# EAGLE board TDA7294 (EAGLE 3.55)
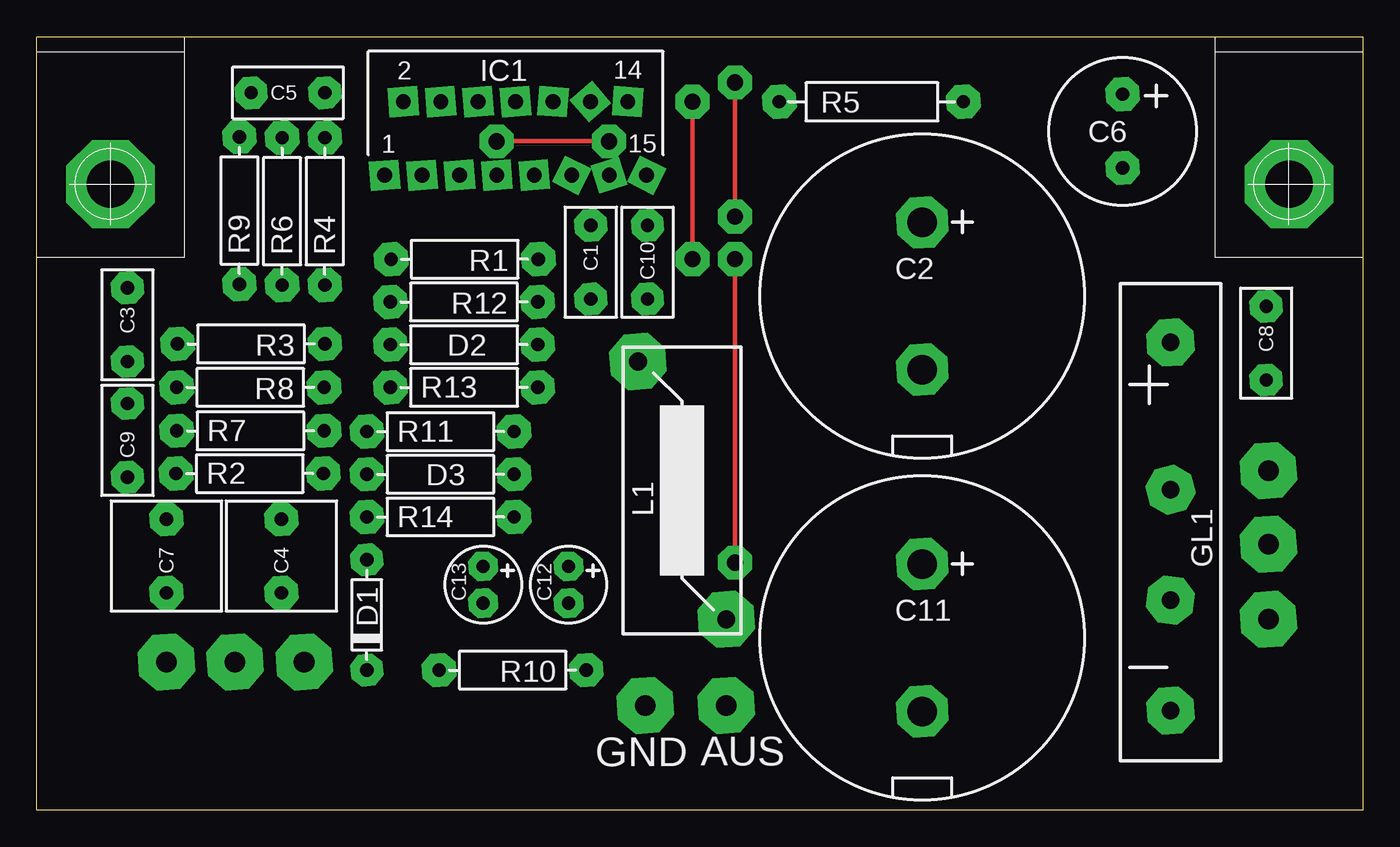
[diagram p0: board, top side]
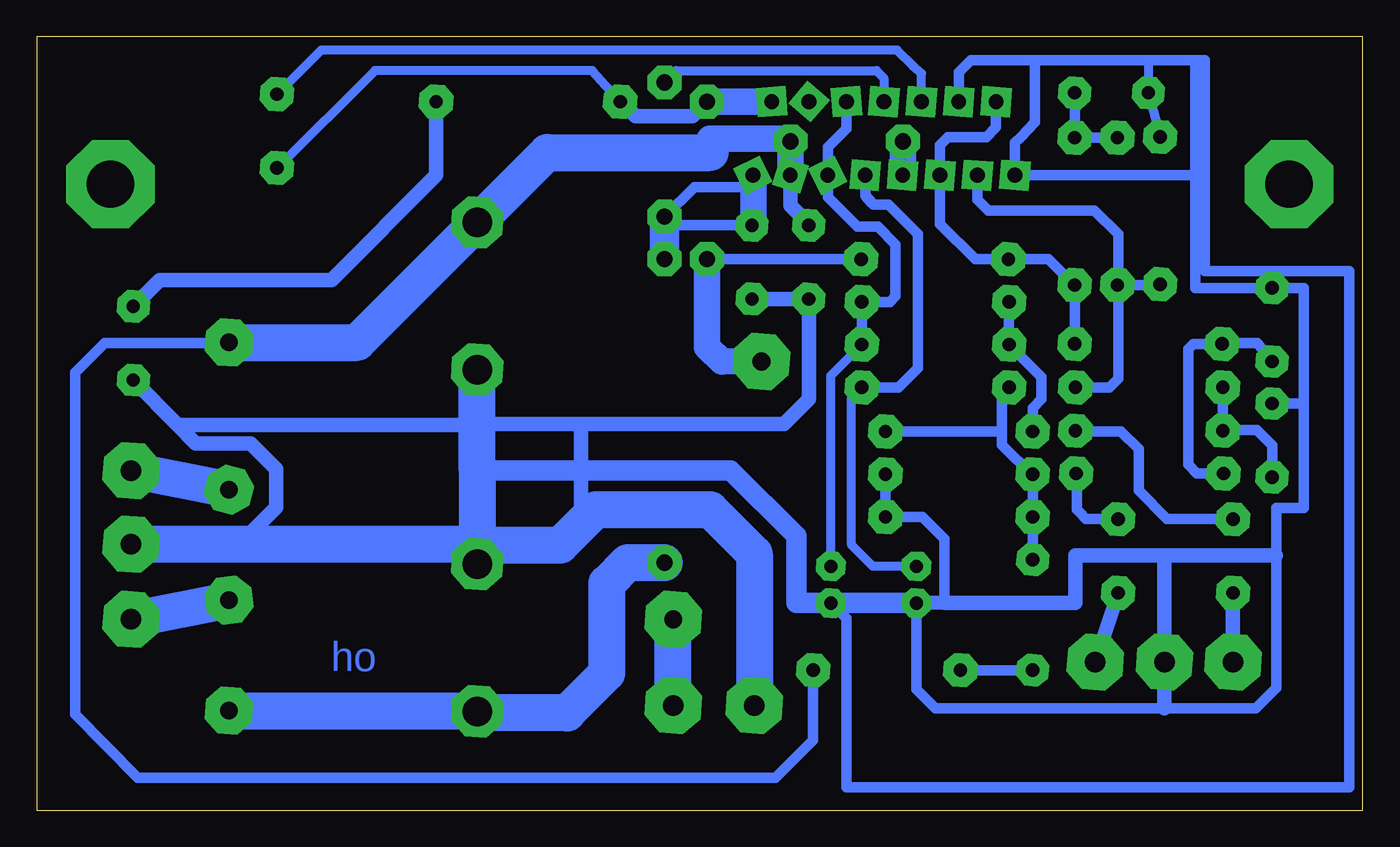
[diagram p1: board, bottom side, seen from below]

Size 90 x 52.5 mm. Coordinates in mm from the lower left corner, seen from the top.
Outline: 0,0 0,52.5 90,52.5 90,0 0,0
Copper layers used: Top, Bottom

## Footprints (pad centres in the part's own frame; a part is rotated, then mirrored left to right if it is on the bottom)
AD-3,8 = drill 1.4 pad 3.8 octagon:  0,0
-3,5 = drill 0.9 pad 2.2 octagon:  0,0;  5,0
22-R10 = drill 2 pad 3.5 octagon:  0,-5;  0,5
-7,5 = drill 0.9 pad 2.3 octagon:  0,0;  5,0
0-R5 = drill 0.9 pad 2.3 octagon:  0,0;  0,5
5-R2,5 = drill 0.9 pad 2 octagon:  0,0;  0,2.5
7,5 = drill 0.9 pad 2.2 octagon:  0,0;  7.5,0
10 = drill 0.9 pad 2.3 octagon:  0,0;  10,0
0C3000 = drill 1.2 pad 3.2 octagon:  0,0;  10.008,0;  17.501,0;  24.994,0
LTI-15 = drill 1 pad 2 square:  0,-4.4;  -1.27,-9.4;  1.27,-9.4;  2.54,-4.4;  5.08,-4.4;  7.62,-4.4;  -2.54,-4.4;  -5.08,-4.4;  -7.62,-4.4;  3.81,-9.4;  6.35,-9.4;  8.89,-9.4;  -3.81,-9.4;  -6.35,-9.4;  -8.89,-9.4
OSSEL3 = drill 1.2 pad 3.8 octagon:  0,0;  17.501,5.994
12,5 = drill 0.9 pad 2.3 octagon:  0,0;  12.5,0

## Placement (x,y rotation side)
+AUS  +Aus  [AD-3,8]  46.8,7.1 0 top
+EIN  +Ein  [AD-3,8]  8.8,10.05 0 top
-AUS  [AD-3,8]  83.6,18.05 0 top
-EIN  -Ein  [AD-3,8]  18.15,10.05 0 top
BEF1  [NKEL15]  5,42.5 0 top
BEF2  [NKEL15]  85,42.5 0 top
C1  220n  [-3,5]  37.6,39.7 270 top
C2  4700u  [22-R10]  60.1,34.9 0 top
C3  220p  [-3,5]  6.15,35.45 270 top
C4  2u2  [-7,5]  16.6,14.75 90 top
C5  4n7  [-3,5]  14.55,48.7 0 top
C6  47u  [0-R5]  73.7,43.6 0 top
C7  2u2  [-7,5]  8.8,14.75 90 top
C8  10n  [-3,5]  83.45,34.2 270 top
C9  220p  [-3,5]  6.15,22.6 90 top
C10  220n  [-3,5]  41.45,34.7 90 top
C11  4700u  [22-R10]  60.1,11.7 0 top
C12  10u  [5-R2,5]  36.1,14.05 0 top
C13  10u  [5-R2,5]  30.3,14.05 0 top
D1  ZPD12  [7,5]  22.4,9.5 90 top
D2  1N4148  [10]  24,31.6 0 top
D3  ZPD4.7  [10]  22.4,22.8 0 top
GL1  B80C3000  [0C3000]  76.95,31.75 270 top
IC1  TDA7294  [LTI-15]  32.5,52.5 0 top
L1  5æH  [OSSEL3]  46.8,12.95 90 top
R1  [10]  34.05,37.4 180 top
R2  1k  [10]  9.45,22.85 0 top
R3  10k  [10]  19.55,31.65 180 top
R4  1k  [10]  19.55,35.65 90 top
R5  6R8  [12,5]  50.4,48.1 0 top
R6  1k  [10]  16.65,35.65 90 top
R7  1k  [10]  9.5,25.75 0 top
R8  10k  [10]  19.5,28.7 180 top
R9  [10]  13.75,35.7 90 top
R10  3k9  [10]  37.3,9.5 180 top
R11  10k  [10]  22.4,25.7 0 top
R12  30k  [10]  34,34.5 180 top
R13  18k  [10]  24,28.7 0 top
R14  1k8  [10]  22.4,19.9 0 top
U$22  GND  [AD-3,8]  13.45,10.05 0 top
U$27  AC  [AD-3,8]  83.6,12.95 0 top
U$28  AC  [AD-3,8]  83.6,23.05 0 top
U$29  GND  [AD-3,8]  41.3,7.1 0 top

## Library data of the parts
+AUS +EIN -AUS -EIN U$22 U$27-U$29 = PADS
BEF1 BEF2 = MECHANIK
C1 C3-C10 C12 C13 D1-D3 R1-R14 = EAGLE
C2 C11 = ELKOS
GL1 L1 = SPEZIAL
IC1 = LEIST-IC

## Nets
+AUS: +AUS. L1.
+EIN: +EIN. C7.
+UB: C1. C2. GL1. IC1. R10.
-EIN: -EIN. C4.
-UB: C10. C11. GL1. IC1.
AC1: GL1. U$27.
AC2: GL1. U$28.
GND: -AUS. C1. C2. C3. C5. C8. C9. C10. C11. C12. C13. D3. IC1. R9. R14. U$22. U$29.
MUTE: C12. D2. IC1. R12.
N$1: IC1. R1. R3. R4.
N$2: IC1. R6. R8. R9.
N$3: C6. IC1.
N$5: C3. R2. R3.
N$6: C9. R7. R8.
N$7: C5. R4. R6.
N$8: C4. R2.
N$9: C7. R7.
N$12: C8. R5.
N$13: C6. IC1. L1. R1. R5.
N$14: D1. R10.
N$15: D1. D3. R11. R13. R14.
N$22: D2. R11. R12.
STBY: C13. IC1. R13.

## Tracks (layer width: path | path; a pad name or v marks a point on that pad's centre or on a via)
+AUS
  Bottom 2.5: +AUS. 46.8,12.95
+EIN
  Bottom 1: +EIN. 8.8,14.75
+UB  (via drill 1.1 pad 2.3)
  Top 0.3: v38.85,45.4 v31.2,45.4
  Bottom 0.6: 31.2,43.1 31.23,43.1
  Bottom 0.7: 37.3,9.5 37.3,4.75 39.85,2.2 83.15,2.2 87.4,6.5 87.4,29.7 85.4,31.7 76.9,31.7 76.95,31.75 | C2. 60.1,39.85
  Bottom 1: 37.6,39.7 37.55,39.75 38.85,41.05 38.85,43.1
  Bottom 1.8: 38.85,43.1 v38.85,45.4 38.9,45.4 38.9,45.6 44.3,45.6 44.3,44.65 | v31.2,45.4 31.2,43.1
  Bottom 2.5: 76.95,31.75 68.25,31.75 C2. 55.35,44.65 44.3,44.65
-EIN
  Bottom 1: -EIN. 16.6,14.75
-UB  (via drill 1.1 pad 2.3)
  Top 0.3: v47.4,40.3 v47.4,49.4 | v47.4,16.8 v47.4,37.4
  Bottom 0.425: 41.39,43.1 41.4,43.1
  Bottom 0.6: 32.5,48.1 32.5,49.7 33,50.2 46.6,50.2 v47.4,49.4
  Bottom 0.7: v47.4,40.3 45.35,42.3 42.15,42.3 41.4,43.05 41.39,43.1 | C10. 47.5,39.7
  Bottom 1.8: C10. 41.35,39.7 41.35,43.1 41.39,43.1
  Bottom 2: v47.4,37.4 v47.4,40.3
  Bottom 2.5: GL1. 76.85,6.7 60.1,6.7 60.15,6.65 60.15,6.6 54,6.6 51.3,9.3 51.3,15.4 49.9,16.8 v47.4,16.8
AC1
  Bottom 2.5: U$27. 83.6,12.9 76.95,14.25
AC2
  Bottom 2.5: 76.95,21.74 U$28.
GND
  Bottom 0.35: IC1. | 28.35,14.05 28.4,14.05
  Bottom 0.525: 30.3,14.05 30.3,14.1
  Bottom 0.6: 14.55,50.95 14.55,50.9 14.55,48.7 R9.
  Bottom 0.7: 22.25,50.9 14.55,50.9 10.7,50.9 10.7,43.1 | 10.7,43.1 10.7,36.6 0.9,36.6 0.9,1.55 35.05,1.55 35.05,13 36.1,14.05 | 22.25,50.9 22.25,46.7 23.2,45.7 23.6,45.3 IC1. 11.35,43.1 | 22.25,50.9 26.6,50.9 27.4,50.1 27.4,48.1 27.42,48.1 | 4,27.6 C9. | D3. R14. 29.9,19.9 28.4,18.4 28.4,14.05 | 4,27.6 4,20.5 5.85,20.5 5.85,8.3 7.25,6.9 13.45,6.9 29,6.9 30.3,8.2 30.3,14.05 | 10.7,43.1 11.35,43.1 | 11.35,43.1 11.35,50.9 | 11.35,43.1 11.35,35.45 6.15,35.45 4,35.45 4,27.6
  Bottom 1: 41.45,34.7 C1. 37.6,27.9 39.3,26.2 53.05,26.2 | 60.1,26.2 53.05,26.2 | 13.45,17.3 19.5,17.3 19.5,14.05 28.35,14.05 30.3,14.1 | 60.1,26.15 80.45,26.15 | 80.45,26.15 C8. | 53.05,26.2 53.05,19.25 | 75.7,18.6 73.75,20.55 73.75,23.15 75.5,24.9 79.2,24.9 80.45,26.15 | 13.45,17.3 5.9,17.3 | 13.45,17.3 U$22. 13.45,6.9
  Bottom 1.25: 60.1,18.05 60.15,18
  Bottom 1.4: 60.1,23.05 42.9,23.05 38.45,18.6 38.45,14.05 36.1,14.05 30.3,14.05
  Bottom 2.5: 60.1,18.05 C11. 60.1,16.65 | 60.1,26.15 60.1,23.05 60.1,18.05 | 60.1,26.15 60.1,26.2 | 60.1,26.15 60.1,29.9 | 60.1,18.05 -AUS. | U$29. 41.3,17.4 44.3,20.4 52.05,20.4 54.45,18 60.15,18
MUTE
  Bottom 0.6: D2. 36.1,29.5 C12.
  Bottom 0.7: 35.04,48.1 35.05,46.25 36.3,45 36.3,41.6 34.3,39.6 32.9,39.6 31.7,38.4 31.7,34.9 32.1,34.5 34,34.5 D2.
N$1
  Bottom 0.35: 28.7,43.1 28.7,43.15
  Bottom 0.7: 24.88,48.1 24.9,46.35 25.55,45.7 28.15,45.7 28.7,45.15 28.7,43.15 | 28.7,43.1 28.7,39.8 26.3,37.4 R1. 21.35,37.4 19.55,35.6 | 19.55,31.65 19.55,35.6 | 19.55,35.6 19.55,35.65
N$2
  Bottom 0.7: 13.75,35.7 13.75,35.65 16.6,35.65 | 26.15,43.1 26.15,41.45 25.4,40.7 18.2,40.7 16.6,39.1 16.6,35.65 | 16.6,35.65 16.65,35.65 | 16.6,35.65 16.6,35.7 | 16.6,35.65 16.6,29.3 17.2,28.7 19.5,28.7
N$3
  Bottom 0.6: 29.96,48.1 29.95,50 30.5,50.5 31.6,51.6 70.7,51.6 C6.
N$4  (via drill 3.2 pad 6)
  other vias: 5,42.5
N$5
  Bottom 0.35: R3. 9.55,31.6
  Bottom 0.7: 9.45,22.85 11.25,22.85 11.85,23.45 11.85,31.3 11.5,31.65 R3. | 9.55,31.6 9.5,31.65 R3. | R3. 9.55,31.7 7.15,31.7 C3.
N$6
  Bottom 0.7: 9.5,25.8 R8. | 6.15,22.6 6.15,24.75 7.2,25.8 9.5,25.8 | 9.5,25.8 9.5,25.75
N$7
  Bottom 0.7: C5. R4. R6.
N$8
  Bottom 0.7: C4. 18.8,19.75 19.2,20.2 19.4,20.4 19.4,22.9 R2.
N$9
  Bottom 0.7: C7. 13.3,19.75 15.2,21.7 15.2,24.5 16.4,25.7 19.5,25.7 R7. 19.5,25.8
N$12
  Bottom 1: 83.45,34.2 81.65,36 70,36 62.9,43.1 R5.
N$13  (via drill 1.1 pad 2.3)
  Top 0.3: v44.5,37.4 v44.5,48.1
  Bottom 0.6: 50.4,48.1 52.3,50.2 67.05,50.2 73.65,43.6 73.7,43.6
  Bottom 0.7: 34.05,37.4 v44.5,37.4
  Bottom 1: v44.5,48.1 45.5,47.1 49.35,47.1 50.4,48.1
  Bottom 1.8: v44.5,48.1 40.12,48.1 | v44.5,37.4 44.5,31.45 43.5,30.45 40.8,30.5 L1.
N$14
  Bottom 0.7: 22.4,9.5 R10.
N$15
  Bottom 0.7: 24,28.7 24.5,28.2 24.5,25.7 | 24.5,25.7 24.5,24.8 22.4,22.7 | 24.5,25.7 R11. | 22.4,22.7 22.4,19.9 D1. | 22.4,22.7 22.4,22.8
N$16  (via drill 3.2 pad 6)
  other vias: 85,42.5
N$22
  Bottom 0.7: R12. 24,31.6 21.8,29.4 21.8,27.9 22.4,27.3 22.4,25.7
STBY
  Bottom 0.6: R13. 34.7,28 34.7,18 33.25,16.55 C13.
  Bottom 0.7: 33.77,43.1 33.75,41.7 33.3,41.2 33.2,41.1 32.2,41.1 30.2,39.1 30.2,30 31.5,28.7 R13.

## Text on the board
Bottom: ho
tPlace: GND | AUS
